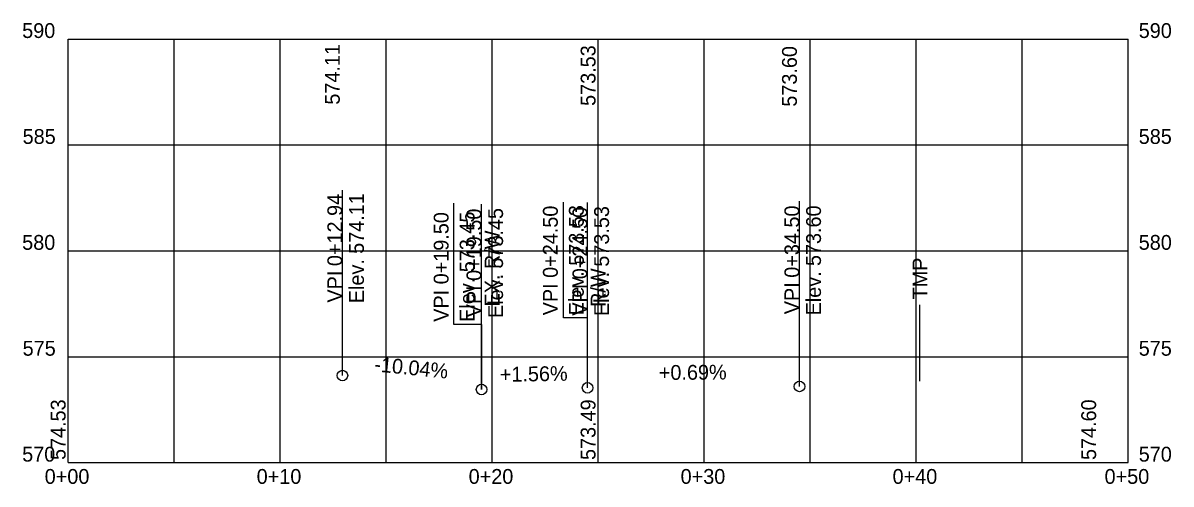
# Model space of a CAD drawing. Extents: x -2.1 to 52, y 569 to 590.8.
import ezdxf

# ---------------------------------------------------------------- set-up
doc = ezdxf.new("R2010")
doc.units = 0
for name, color, linetype in [('DV_X_Lot_Line', 7, 'Continuous'), ('DV_X_Property_Line', 7, 'Continuous'), ('GE_P_Alignment', 7, 'Continuous'), ('GE_X_Alignment', 7, 'Continuous'), ('PF_X_Ground_Line', 7, 'Continuous'), ('RW_P_Taking_Area', 7, 'Continuous'), ('RW_X_Text', 7, 'Continuous'), ('SH_Text', 7, 'Continuous')]:
    doc.layers.add(name, color=color, linetype=linetype)

msp = doc.modelspace()

# ---------------------------------------------------------------- linework, layer by layer
at = {"layer": 'GE_P_Alignment'}
msp.add_line((19.999, 573.51), (19.999, 577.121), dxfattribs=at)
at = {"layer": 'GE_X_Alignment'}
msp.add_line((40.182, 573.845), (40.182, 577.456), dxfattribs=at)
at = {"layer": 'PF_X_Ground_Line'}
for p, q in [((0, 590), (50, 590)), ((0, 570), (0, 590)), ((0, 590), (50, 590)), ((0, 570), (0, 590)), ((5, 570), (5, 590)), ((5, 570), (5, 590)), ((10, 570), (10, 590)), ((10, 570), (10, 590)), ((15, 570), (15, 590)), ((15, 570), (15, 590)), ((20, 570), (20, 590)), ((20, 570), (20, 590)), ((25, 570), (25, 590)), ((25, 570), (25, 590)), ((30, 570), (30, 590)), ((30, 570), (30, 590)), ((35, 570), (35, 590)), ((35, 570), (35, 590)), ((40, 570), (40, 590)), ((40, 570), (40, 590)), ((45, 570), (45, 590)), ((45, 570), (45, 590)), ((50, 570), (50, 590)), ((50, 570), (50, 590)), ((0, 585), (50, 585)), ((0, 585), (50, 585)), ((0, 580), (50, 580)), ((0, 580), (50, 580)), ((0, 575), (50, 575)), ((0, 575), (50, 575)), ((0, 570), (50, 570)), ((0, 570), (50, 570))]:
    msp.add_line(p, q, dxfattribs=at)
at = {"layer": 'RW_P_Taking_Area'}
for p, q in [((12.936, 574.112), (12.936, 582.862)), ((24.499, 573.531), (24.499, 582.281)), ((34.499, 573.6), (34.499, 582.35)), ((19.499, 573.453), (19.499, 582.203)), ((19.499, 576.53), (19.499, 573.453))]:
    msp.add_line(p, q, dxfattribs=at)
for points in [[(19.499, 576.53), (18.183, 576.53), (18.183, 582.253)], [(24.499, 573.531), (24.499, 576.837), (23.362, 576.837), (23.362, 582.305)]]:
    msp.add_lwpolyline(points, dxfattribs=at)
for centre in [(12.936, 574.112), (19.499, 573.453), (19.499, 573.453), (24.499, 573.531), (24.499, 573.531), (34.499, 573.6)]:
    msp.add_circle(centre, 0.25, dxfattribs=at)
at = {"layer": 'SH_Text'}
msp.add_line((25, 573.492), (25, 577.103), dxfattribs=at)

# ---------------------------------------------------------------- texts
at = {"layer": 'DV_X_Lot_Line'}
for s, p in [('574.53', (-0.125, 570.125)), ('573.49', (24.875, 570.125)), ('574.60', (48.49, 570.125))]:
    msp.add_text(s, height=0.7, rotation=90, dxfattribs=at).set_placement(p)
at = {"layer": 'DV_X_Property_Line'}
for s, p in [('590', (-2.173, 590.05)), ('590', (-2.173, 590.05)), ('590', (50.5, 590.05)), ('590', (50.5, 590.05)), ('585', (-2.152, 585.05)), ('585', (-2.152, 585.05)), ('585', (50.5, 585.05)), ('585', (50.5, 585.05)), ('580', (-2.173, 580.05)), ('580', (-2.173, 580.05)), ('580', (50.5, 580.05)), ('580', (50.5, 580.05)), ('575', (-2.152, 575.05)), ('575', (-2.152, 575.05)), ('575', (50.5, 575.05)), ('575', (50.5, 575.05)), ('570', (-2.173, 570.05)), ('570', (-2.173, 570.05)), ('570', (50.5, 570.05)), ('570', (50.5, 570.05)), ('0+00', (-1.111, 569)), ('0+00', (-1.111, 569)), ('0+10', (8.889, 569)), ('0+10', (8.889, 569)), ('0+20', (18.889, 569)), ('0+20', (18.889, 569)), ('0+30', (28.889, 569)), ('0+30', (28.889, 569)), ('0+40', (38.889, 569)), ('0+40', (38.889, 569)), ('0+50', (48.889, 569)), ('0+50', (48.889, 569))]:
    msp.add_text(s, height=0.7, dxfattribs=at).set_placement(p)
at = {"layer": 'GE_P_Alignment'}
msp.add_text('EX. R/W', height=0.7, rotation=90, dxfattribs=at).set_placement((20.349, 577.372))
at = {"layer": 'GE_X_Alignment'}
msp.add_text('TMP', height=0.7, rotation=90, dxfattribs=at).set_placement((40.532, 577.707))
at = {"layer": 'RW_P_Taking_Area'}
for s, rotation, p in [('0+12.94', 90, (12.925, 579.28)), ('574.11', 90, (13.947, 579.859)), ('VPI 0+19.50', 90, (17.942, 576.65)), ('Elev. 573.45', 90, (19.167, 576.65)), ('0+19.50', 90, (19.488, 578.584)), ('573.45', 90, (20.511, 579.159)), ('VPI 0+24.50', 90, (23.094, 576.956)), ('Elev. 573.53', 90, (24.319, 576.956)), ('0+24.50', 90, (24.488, 578.662)), ('573.53', 90, (25.511, 579.251)), ('0+34.50', 90, (34.488, 578.731)), ('573.60', 90, (35.511, 579.282)), ('Elev. ', 90, (13.947, 577.529)), ('VPI ', 90, (12.925, 577.557)), ('Elev. ', 90, (20.511, 576.829)), ('Elev. ', 90, (25.511, 576.921)), ('Elev. ', 90, (35.511, 576.952)), ('VPI ', 90, (19.488, 576.861)), ('VPI ', 90, (24.488, 576.939)), ('VPI ', 90, (34.488, 577.008)), ('-10.04%', 354.2695, (14.416, 574.313)), ('+1.56%', 0.8937, (20.363, 573.816)), ('+0.69%', 0.3943, (27.862, 573.904))]:
    msp.add_text(s, height=0.7, rotation=rotation, dxfattribs=at).set_placement(p)
at = {"layer": 'RW_X_Text'}
for s, p in [('574.11', (12.811, 586.903)), ('573.53', (24.875, 586.843)), ('573.60', (34.374, 586.806))]:
    msp.add_text(s, height=0.7, rotation=90, dxfattribs=at).set_placement(p)
at = {"layer": 'SH_Text'}
msp.add_text('R/W', height=0.7, rotation=90, dxfattribs=at).set_placement((25.35, 577.354))

doc.saveas('drawing.dxf')
